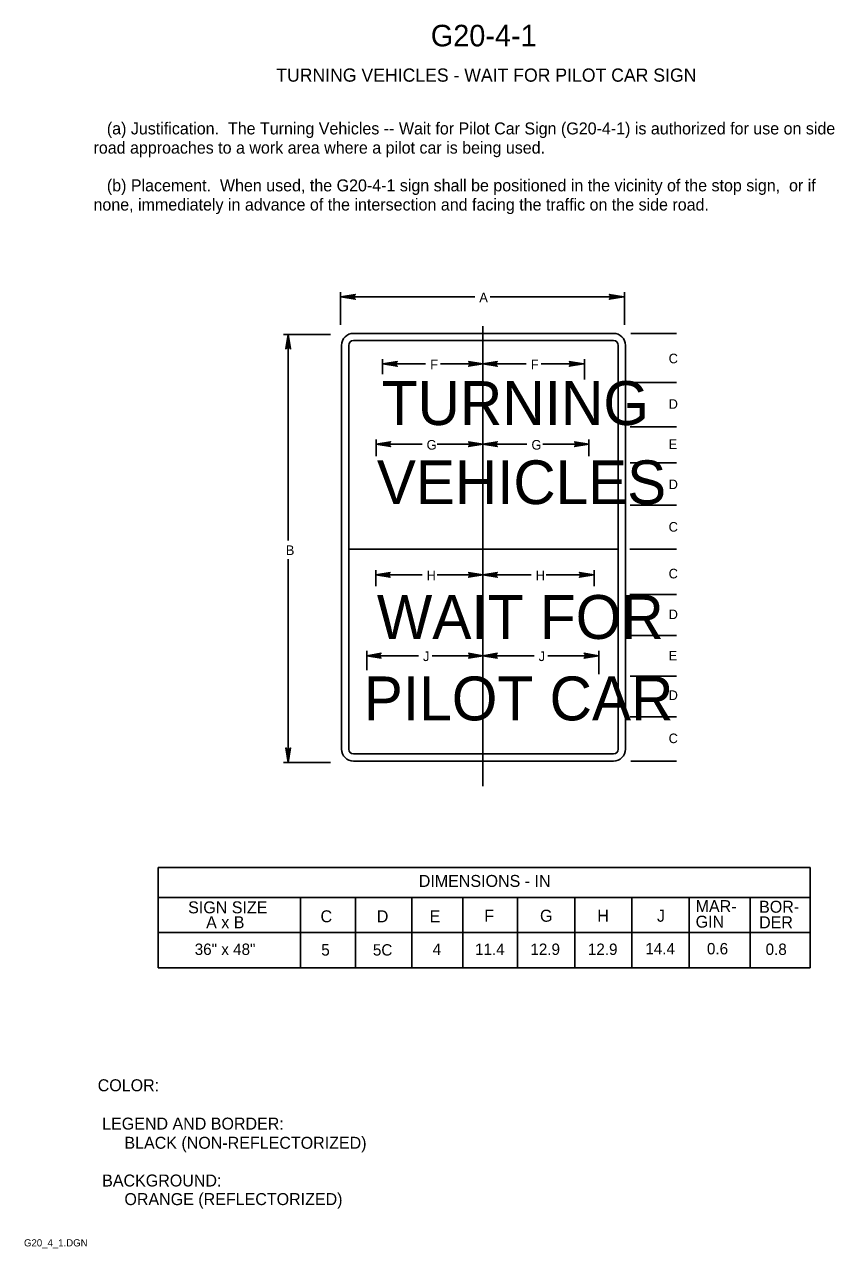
# Model space of a CAD drawing. Extents: x 0.013 to 0.182, y 0.004 to 0.259.
import ezdxf

# ---------------------------------------------------------------- set-up
doc = ezdxf.new("R2010")
doc.units = 0
for name, color, linetype in [('1', 7, 'Continuous'), ('2', 7, 'Continuous'), ('3', 7, 'Continuous'), ('7', 7, 'Continuous')]:
    doc.layers.add(name, color=color, linetype=linetype)

# ---------------------------------------------------------------- blocks, each defined once
blk = doc.blocks.new('RARROW')
at = {"layer": '3'}
blk.add_lwpolyline([(-2.2695, 0.285), (-2.184875, 0.12075), (0, 0), (-2.2695, 0.285), (-2.38575, 0.384625), (0, 0), (-2.183125, -0.108), (-2.262875, -0.2705), (0, 0), (-2.38575, -0.379125), (-2.262875, -0.2705)], dxfattribs=at)

msp = doc.modelspace()

# ---------------------------------------------------------------- linework, layer by layer
at = {"layer": '1'}
for p, q in [((0.17651, 0.08345), (0.17651, 0.0625)), ((0.15126, 0.07718), (0.15126, 0.0625)), ((0.16401, 0.07718), (0.16401, 0.0625))]:
    msp.add_line(p, q, dxfattribs=at)
at = {"layer": '2'}
for p, q in [((0.0405, 0.08345), (0.17651, 0.08345)), ((0.04051, 0.08343), (0.04051, 0.0625)), ((0.0405, 0.0772), (0.17651, 0.0772)), ((0.07021, 0.07718), (0.07021, 0.0625)), ((0.08167, 0.07718), (0.08167, 0.0625)), ((0.09342, 0.07718), (0.09342, 0.0625)), ((0.10405, 0.07718), (0.10405, 0.0625)), ((0.11546, 0.07718), (0.11546, 0.0625)), ((0.12743, 0.07718), (0.12743, 0.0625)), ((0.1393, 0.07718), (0.1393, 0.0625)), ((0.0405, 0.06985), (0.17651, 0.06985)), ((0.0405, 0.0625), (0.17651, 0.0625))]:
    msp.add_line(p, q, dxfattribs=at)
at = {"layer": '3'}
for p, q in [((0.07854, 0.19662), (0.07854, 0.2035)), ((0.10654, 0.2025), (0.07854, 0.2025)), ((0.10979, 0.2025), (0.13779, 0.2025)), ((0.13779, 0.19662), (0.13779, 0.2035)), ((0.07642, 0.19462), (0.06667, 0.19462)), ((0.06763, 0.15163), (0.06763, 0.19462)), ((0.08125, 0.19487), (0.1355, 0.19487)), ((0.13912, 0.19487), (0.14863, 0.19487)), ((0.07875, 0.10812), (0.07875, 0.19237)), ((0.08025, 0.10812), (0.08025, 0.19237)), ((0.08125, 0.19337), (0.1355, 0.19337)), ((0.1365, 0.19237), (0.1365, 0.10812)), ((0.138, 0.19237), (0.138, 0.10812)), ((0.08729, 0.18637), (0.08729, 0.1895)), ((0.10825, 0.18912), (0.10825, 0.1875)), ((0.12942, 0.18525), (0.12942, 0.1895)), ((0.09629, 0.1885), (0.08729, 0.1885)), ((0.09942, 0.1885), (0.10829, 0.1885)), ((0.11729, 0.1885), (0.10829, 0.1885)), ((0.12042, 0.1885), (0.12942, 0.1885)), ((0.139, 0.18463), (0.14863, 0.18463)), ((0.139, 0.17538), (0.14863, 0.17538)), ((0.086, 0.16925), (0.086, 0.17275)), ((0.09554, 0.17175), (0.08604, 0.17175)), ((0.09867, 0.17175), (0.10829, 0.17175)), ((0.10825, 0.17262), (0.10825, 0.17075)), ((0.11744, 0.17175), (0.10829, 0.17175)), ((0.12075, 0.17175), (0.13037, 0.17175)), ((0.13037, 0.16925), (0.13037, 0.17275)), ((0.139, 0.16787), (0.14863, 0.16787)), ((0.139, 0.159), (0.14863, 0.159)), ((0.1365, 0.14988), (0.08025, 0.14988)), ((0.13887, 0.14988), (0.14863, 0.14988)), ((0.06763, 0.14776), (0.06763, 0.10537)), ((0.08589, 0.14212), (0.08589, 0.1455)), ((0.09554, 0.1445), (0.08592, 0.1445)), ((0.09867, 0.1445), (0.10829, 0.1445)), ((0.10825, 0.14374), (0.10825, 0.14549)), ((0.11829, 0.1445), (0.10829, 0.1445)), ((0.12142, 0.1445), (0.13146, 0.1445)), ((0.13146, 0.14212), (0.13146, 0.1455)), ((0.13887, 0.14037), (0.14863, 0.14037)), ((0.13887, 0.13187), (0.14863, 0.13187)), ((0.084, 0.12463), (0.084, 0.12863)), ((0.10825, 0.12625), (0.10825, 0.12863)), ((0.13242, 0.12375), (0.13242, 0.12862)), ((0.09479, 0.12762), (0.08404, 0.12762)), ((0.09767, 0.12762), (0.10829, 0.12762)), ((0.11892, 0.12762), (0.10829, 0.12762)), ((0.12179, 0.12762), (0.13242, 0.12762)), ((0.139, 0.12337), (0.14863, 0.12337)), ((0.139, 0.11488), (0.14863, 0.11488)), ((0.07642, 0.10537), (0.06667, 0.10537)), ((0.1355, 0.10712), (0.08125, 0.10712)), ((0.1355, 0.10562), (0.08125, 0.10562)), ((0.13912, 0.10562), (0.14863, 0.10562))]:
    msp.add_line(p, q, dxfattribs=at)
for centre, radius, start, end in [((0.08125, 0.19237), 0.0025, 90, 180), ((0.1355, 0.19237), 0.0025, 0, 90), ((0.08125, 0.19237), 0.001, 90, 180), ((0.1355, 0.19237), 0.001, 0, 90), ((0.08125, 0.10812), 0.0025, 180, 270), ((0.08125, 0.10812), 0.001, 180, 270), ((0.1355, 0.10812), 0.0025, 270, 0), ((0.1355, 0.10812), 0.001, 270, 0)]:
    msp.add_arc(centre, radius, start, end, dxfattribs=at)
at = {"layer": '7'}
for p, q in [((0.10825, 0.19637), (0.10825, 0.13712)), ((0.10825, 0.18663), (0.10825, 0.18663)), ((0.10825, 0.17263), (0.10825, 0.17263)), ((0.10825, 0.15788), (0.10825, 0.10038)), ((0.10825, 0.142), (0.10825, 0.142)), ((0.10825, 0.12788), (0.10825, 0.12788))]:
    msp.add_line(p, q, dxfattribs=at)

# ---------------------------------------------------------------- block references
at = {"layer": '3'}
for p, xscale, yscale, rotation in [((0.07863, 0.2025), 0.0012574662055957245, 0.001309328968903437, 180), ((0.06763, 0.19462), 0.0012574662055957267, -0.0013093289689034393, 90), ((0.08738, 0.1885), 0.0012574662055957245, 0.001309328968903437, 180), ((0.10825, 0.1885), 0.0012574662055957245, 0.001309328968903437, 180), ((0.086, 0.17175), 0.0012574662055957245, 0.001309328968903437, 180), ((0.10825, 0.17175), 0.0012574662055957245, 0.001309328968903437, 180), ((0.08588, 0.1445), 0.0012574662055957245, 0.001309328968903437, 180), ((0.10825, 0.1445), 0.0012574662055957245, 0.001309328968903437, 180), ((0.084, 0.12763), 0.0012574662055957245, 0.001309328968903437, 180), ((0.10825, 0.12763), 0.0012574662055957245, 0.001309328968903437, 180), ((0.06763, 0.10537), 0.0012574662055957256, 0.0013093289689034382, -90.00000000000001)]:
    msp.add_blockref('RARROW', p, dxfattribs=dict(at, xscale=xscale, yscale=yscale, rotation=rotation))
at = {"layer": '3', "xscale": 0.0012574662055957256, "yscale": -0.0013093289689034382}
for p in [(0.13762, 0.2025), (0.10825, 0.1885), (0.12925, 0.1885), (0.10825, 0.17175), (0.13037, 0.17175), (0.10825, 0.1445), (0.13137, 0.1445), (0.10825, 0.12763), (0.13237, 0.12763)]:
    msp.add_blockref('RARROW', p, dxfattribs=at)

# ---------------------------------------------------------------- texts
at = {"layer": '1'}
for s, height, p in [('G20-4-1', 0.0045, (0.09738, 0.25475)), ('TURNING VEHICLES - WAIT FOR PILOT CAR SIGN', 0.0027503, (0.06513, 0.24738)), ('0.6', 0.002375, (0.15499, 0.06531)), ('0.8', 0.002375, (0.16723, 0.06519)), ('COLOR:', 0.0025, (0.02788, 0.03675)), (' LEGEND AND BORDER:', 0.0024998, (0.02788, 0.02875)), ('      BLACK (NON-REFLECTORIZED)', 0.0024998, (0.02788, 0.02475)), (' BACKGROUND:', 0.0024998, (0.02788, 0.01688)), ('      ORANGE (REFLECTORIZED)', 0.0024998, (0.02788, 0.013)), ('G20_4_1.DGN', 0.0015, (0.0125, 0.00438))]:
    msp.add_text(s, height=height, dxfattribs=at).set_placement(p)
at = {"layer": '2'}
for s, height, p in [('   (a) Justification.  The Turning Vehicles -- Wait for Pilot Car Sign (G20-4-1) is authorized for use on side ', 0.00249975, (0.027, 0.23638)), ('road approaches to a work area where a pilot car is being used.', 0.0024998, (0.027, 0.23237)), ('   (b) Placement.  When used, the G20-4-1 sign shall be positioned in the vicinity of the stop sign,  or if ', 0.00249975, (0.027, 0.2245)), ('none, immediately in advance of the intersection and facing the traffic on the side road.', 0.0024998, (0.027, 0.2205)), ('DIMENSIONS - IN', 0.0024998, (0.09487, 0.07938)), ('SIGN SIZE', 0.0025, (0.04675, 0.07387)), ('C', 0.0025, (0.07437, 0.072)), ('D', 0.0025, (0.08611, 0.072)), ('E', 0.0025, (0.09713, 0.072)), ('F', 0.0025, (0.10852, 0.07212)), ('G', 0.0025, (0.12016, 0.07212)), ('H', 0.0025, (0.13211, 0.07212)), ('A x B', 0.0025, (0.0505, 0.07075))]:
    msp.add_text(s, height=height, dxfattribs=at).set_placement(p)
at = {"layer": '3'}
for s, height, p in [('A', 0.002, (0.1075, 0.20137)), ('F', 0.002, (0.09725, 0.18738)), ('F', 0.002, (0.11825, 0.18738)), ('C', 0.002, (0.147, 0.18863)), ('D', 0.002, (0.147, 0.17913)), ('G', 0.002, (0.0965, 0.17062)), ('G', 0.002, (0.11838, 0.17062)), ('E', 0.002, (0.147, 0.17075)), ('D', 0.002, (0.147, 0.16237)), ('C', 0.002, (0.147, 0.1535)), ('B', 0.002, (0.06713, 0.14863)), ('C', 0.002, (0.147, 0.14375)), ('H', 0.002, (0.0965, 0.14338)), ('H', 0.002, (0.11925, 0.14338)), ('D', 0.002, (0.147, 0.13525)), ('J', 0.002, (0.09575, 0.1265)), ('J', 0.002, (0.11988, 0.1265)), ('E', 0.002, (0.147, 0.12663)), ('D', 0.002, (0.147, 0.11838)), ('C', 0.002, (0.147, 0.10938)), ('MAR-', 0.0025, (0.15263, 0.07412)), ('J', 0.0025, (0.14456, 0.07212)), ('BOR-', 0.0025, (0.16587, 0.074)), ('GIN', 0.0025, (0.15263, 0.07088)), ('DER', 0.0025, (0.16587, 0.07075)), ('36" x 48"', 0.002375, (0.04812, 0.06519)), ('5', 0.00238, (0.07452, 0.06506)), ('5C', 0.002375, (0.08529, 0.06506)), ('4', 0.00238, (0.09776, 0.06519)), ('11.4', 0.002375, (0.1066, 0.06519)), ('12.9', 0.002375, (0.11815, 0.06519)), ('12.9', 0.002375, (0.13015, 0.06519)), ('14.4', 0.002375, (0.14214, 0.06531))]:
    msp.add_text(s, height=height, dxfattribs=at).set_placement(p)
at = {"layer": '7'}
for s, height, p in [('TURNING', 0.009155, (0.08713, 0.17575)), ('VEHICLES', 0.009125, (0.08613, 0.15925)), ('WAIT FOR', 0.009155, (0.08613, 0.13112)), ('PILOT CAR', 0.009155, (0.08338, 0.11413))]:
    msp.add_text(s, height=height, dxfattribs=at).set_placement(p)

doc.saveas('drawing.dxf')
